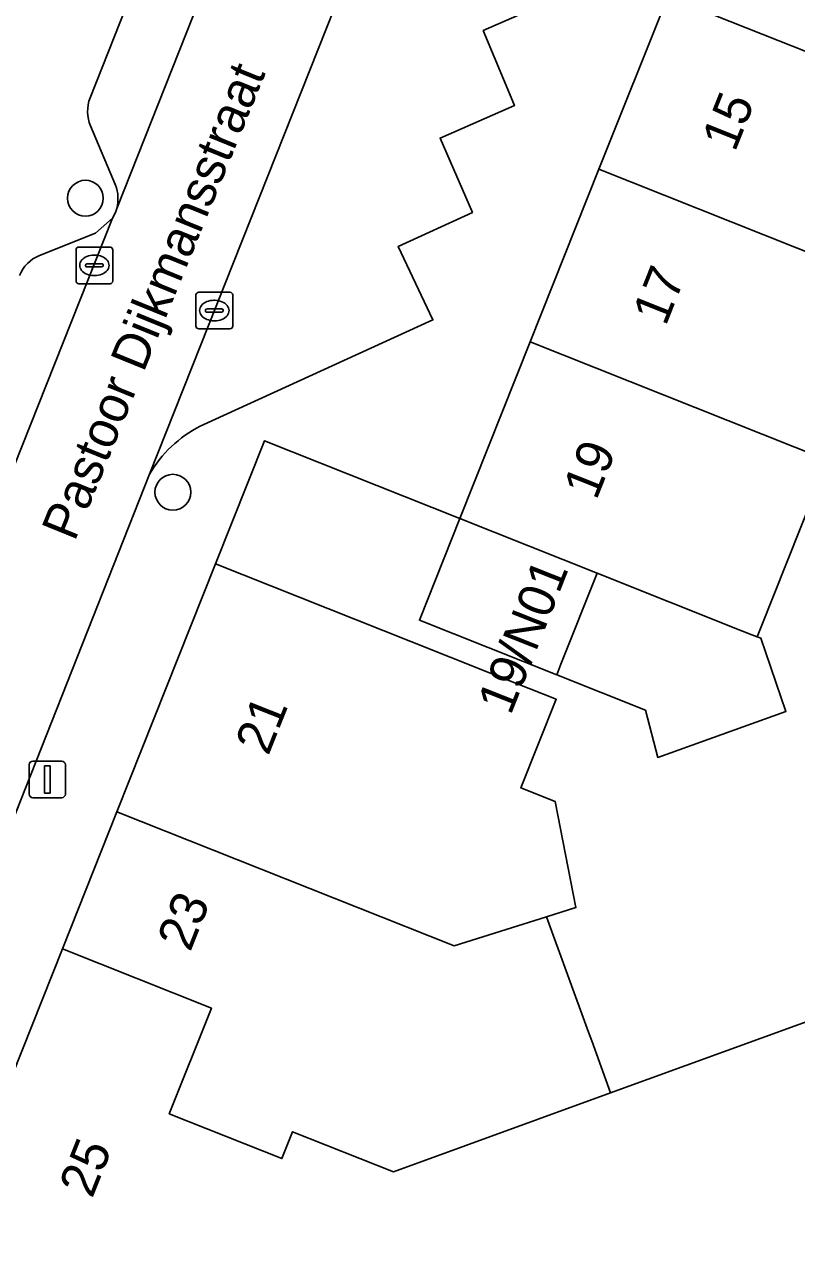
# Model space of a CAD drawing. Extents: x 161798 to 162385, y 382315 to 382833.
# Drawn here: x 162168.1 to 162189.17, y 382526.57 to 382559.91 of the extents above; entities that cross this region are included whole.
import ezdxf

# ---------------------------------------------------------------- set-up
doc = ezdxf.new("R2010")
doc.units = 0
for name, color, linetype in [('IMGEO_Boom', 7, 'Continuous'), ('IMGEO_Erf', 7, 'Continuous'), ('IMGEO_Kolk', 7, 'Continuous'), ('IMGEO_Lichtmast', 7, 'Continuous'), ('IMGEO_Openbare_ruimte_label', 7, 'Continuous'), ('IMGEO_Pand', 7, 'Continuous'), ('IMGEO_Pand_nummerreeks', 7, 'Continuous'), ('IMGEO_Parkeervlak_open', 7, 'Continuous'), ('IMGEO_Rijbaan_lokaal_open', 7, 'Continuous'), ('IMGEO_Voetpad_open', 7, 'Continuous')]:
    doc.layers.add(name, color=color, linetype=linetype)

msp = doc.modelspace()

# ---------------------------------------------------------------- linework, layer by layer
at = {"layer": 'IMGEO_Boom'}
for centre in [(162169.767, 382555.17), (162172.154, 382547.147)]:
    msp.add_circle(centre, 0.489, dxfattribs=at)
at = {"layer": 'IMGEO_Erf'}
msp.add_lwpolyline([(162190.014, 382548.026), (162188.187, 382543.433), (162188.095, 382543.201), (162188.194, 382543.162), (162188.876, 382541.169), (162185.38, 382539.91), (162185.051, 382541.201), (162182.624, 382542.166), (162178.881, 382543.655), (162179.984, 382546.428), (162174.656, 382548.553), (162173.318, 382545.194), (162178.647, 382543.075), (162180.788, 382542.223), (162182.61, 382541.498), (162181.649, 382539.082), (162182.578, 382538.713), (162183.15, 382535.817), (162182.349, 382535.566), (162183.495, 382532.413), (162183.579, 382532.181), (162184.096, 382530.759), (162210.904, 382540.496)], dxfattribs=at)
at = {"layer": 'IMGEO_Kolk'}
for p, q in [((162169.512, 382552.912), (162169.512, 382553.764)), ((162169.587, 382553.838), (162170.439, 382553.838)), ((162170, 382553.618), (162170.025, 382553.618)), ((162170.513, 382553.764), (162170.513, 382552.912)), ((162169.771, 382553.332), (162169.771, 382553.344)), ((162170.209, 382553.295), (162169.811, 382553.295)), ((162169.814, 382553.381), (162170.212, 382553.381)), ((162170.255, 382553.344), (162170.255, 382553.332)), ((162170.023, 382553.058), (162169.998, 382553.058)), ((162170.439, 382552.838), (162169.587, 382552.838)), ((162172.859, 382552.605), (162173.711, 382552.605)), ((162172.784, 382551.679), (162172.784, 382552.531)), ((162173.272, 382552.385), (162173.297, 382552.385)), ((162173.785, 382552.531), (162173.785, 382551.679)), ((162173.043, 382552.099), (162173.043, 382552.111)), ((162173.481, 382552.062), (162173.083, 382552.062)), ((162173.086, 382552.148), (162173.484, 382552.148)), ((162173.527, 382552.111), (162173.527, 382552.099)), ((162173.711, 382551.605), (162172.859, 382551.605)), ((162173.295, 382551.825), (162173.27, 382551.825))]:
    msp.add_line(p, q, dxfattribs=at)
for points in [[(162169.512, 382552.912), (162169.512, 382553.764)], [(162169.587, 382553.838), (162170.439, 382553.838)], [(162170.513, 382553.764), (162170.513, 382552.912)], [(162170.439, 382552.838), (162169.587, 382552.838)], [(162172.859, 382552.605), (162173.711, 382552.605)], [(162172.784, 382551.679), (162172.784, 382552.531)], [(162173.785, 382552.531), (162173.785, 382551.679)], [(162173.711, 382551.605), (162172.859, 382551.605)]]:
    msp.add_lwpolyline(points, dxfattribs=at)
for centre, radius, start, end in [((162169.589, 382553.762), 0.0765, 91.552, 178.448), ((162169.589, 382553.762), 0.0765, 91.552, 178.448), ((162170.437, 382553.762), 0.0765, 1.552, 88.448), ((162170.437, 382553.762), 0.0765, 1.552, 88.448), ((162169.811, 382553.341), 0.0403, 85.8775, 175.7526), ((162169.808, 382553.331), 0.0366, 178.938, 274.7102), ((162170.212, 382553.338), 0.043, 264.8664, 352.4533), ((162170.216, 382553.343), 0.0386, 1.7309, 96.639), ((162169.589, 382552.914), 0.0765, 181.552, 268.448), ((162169.589, 382552.914), 0.0765, 181.552, 268.448), ((162170.437, 382552.914), 0.0765, 271.552, 358.448), ((162170.437, 382552.914), 0.0765, 271.552, 358.448), ((162172.861, 382552.529), 0.0765, 91.552, 178.448), ((162172.861, 382552.529), 0.0765, 91.552, 178.448), ((162173.709, 382552.529), 0.0765, 1.552, 88.448), ((162173.709, 382552.529), 0.0765, 1.552, 88.448), ((162173.083, 382552.108), 0.0403, 85.8775, 175.7526), ((162173.08, 382552.098), 0.0366, 178.938, 274.7102), ((162173.484, 382552.105), 0.043, 264.8664, 352.4533), ((162173.488, 382552.11), 0.0386, 1.7309, 96.639), ((162172.861, 382551.681), 0.0765, 181.552, 268.448), ((162172.861, 382551.681), 0.0765, 181.552, 268.448), ((162173.709, 382551.681), 0.0765, 271.552, 358.448), ((162173.709, 382551.681), 0.0765, 271.552, 358.448)]:
    msp.add_arc(centre, radius, start, end, dxfattribs=at)
for centre, major_axis, ratio, start_param, end_param in [((162169.999, 382553.338), (-0.387, 0.002), 0.722429, 4.712389, 7.853982), ((162170.024, 382553.338), (-0.39, 0.002), 0.717154, 1.570796, 4.712389), ((162173.271, 382552.105), (-0.387, 0.002), 0.722429, 4.712389, 7.853982), ((162173.296, 382552.105), (-0.39, 0.002), 0.717154, 1.570796, 4.712389)]:
    msp.add_ellipse(centre, major_axis=major_axis, ratio=ratio, start_param=start_param, end_param=end_param, dxfattribs=at)
at = {"layer": 'IMGEO_Lichtmast'}
for p, q in [((162168.232, 382538.912), (162168.232, 382539.712)), ((162168.232, 382539.712), (162168.232, 382538.912)), ((162168.332, 382539.812), (162169.122, 382539.812)), ((162169.122, 382539.812), (162168.332, 382539.812)), ((162169.222, 382539.712), (162169.222, 382538.912)), ((162169.222, 382538.912), (162169.222, 382539.712)), ((162169.122, 382538.812), (162168.332, 382538.812)), ((162168.332, 382538.812), (162169.122, 382538.812))]:
    msp.add_line(p, q, dxfattribs=at)
msp.add_lwpolyline([(162168.652, 382539.687), (162168.802, 382539.687), (162168.802, 382538.937), (162168.652, 382538.937), (162168.652, 382539.687)], dxfattribs=at)
for centre, start, end in [((162168.332, 382539.712), 90, 180), ((162168.332, 382539.712), 90, 180), ((162169.122, 382539.712), 0, 90), ((162169.122, 382539.712), 360, 90), ((162168.332, 382538.912), 180, 270), ((162168.332, 382538.912), 180, 270), ((162169.122, 382538.912), 270, 0), ((162169.122, 382538.912), 270, 0)]:
    msp.add_arc(centre, 0.1, start, end, dxfattribs=at)
at = {"layer": 'IMGEO_Pand'}
for points in [[(162195.638, 382562.163), (162187.527, 382565.389), (162185.652, 382560.677), (162193.763, 382557.45)], [(162193.763, 382557.45), (162185.652, 382560.677), (162183.777, 382555.964), (162191.889, 382552.738)], [(162190.014, 382548.026), (162191.889, 382552.738), (162183.777, 382555.964), (162181.903, 382551.252)], [(162190.014, 382548.026), (162181.903, 382551.252), (162179.984, 382546.428), (162183.727, 382544.939), (162187.693, 382543.361), (162187.949, 382543.259), (162188.095, 382543.201), (162188.187, 382543.433)], [(162183.727, 382544.939), (162179.984, 382546.428), (162178.881, 382543.655), (162182.624, 382542.166), (162182.738, 382542.454)], [(162182.61, 382541.498), (162180.788, 382542.223), (162178.647, 382543.075), (162173.318, 382545.194), (162170.627, 382538.431), (162179.823, 382534.773), (162182.349, 382535.566), (162183.15, 382535.817), (162182.578, 382538.713), (162181.649, 382539.082)], [(162188.095, 382543.201), (162187.949, 382543.259), (162187.693, 382543.361), (162183.727, 382544.939), (162182.738, 382542.454), (162182.624, 382542.166), (162185.051, 382541.201), (162185.38, 382539.91), (162188.876, 382541.169), (162188.194, 382543.162)], [(162213.462, 382532.438), (162213.43, 382532.539), (162210.904, 382540.496), (162184.096, 382530.759), (162178.17, 382528.607), (162175.421, 382529.7), (162175.13, 382528.968), (162172.056, 382530.191), (162173.203, 382533.073), (162169.14, 382534.691), (162165.279, 382524.987), (162172.735, 382522.522), (162172.781, 382522.638), (162174.284, 382522.749), (162177.063, 382522.953), (162178.919, 382523.09), (162180.309, 382519.521), (162189.806, 382523.221)], [(162182.349, 382535.566), (162179.823, 382534.773), (162170.627, 382538.431), (162169.14, 382534.691), (162173.203, 382533.073), (162172.056, 382530.191), (162175.13, 382528.968), (162175.421, 382529.7), (162178.17, 382528.607), (162184.096, 382530.759), (162183.579, 382532.181), (162183.495, 382532.413)]]:
    msp.add_lwpolyline(points, close=True, dxfattribs=at)
at = {"layer": 'IMGEO_Parkeervlak_open'}
for points in [[(162170.621, 382554.892), (162178.575, 382574.96)], [(162172.902, 382548.953), (162179.247, 382551.849), (162178.3, 382553.854), (162180.323, 382554.783), (162179.444, 382556.811), (162181.471, 382557.698), (162180.621, 382559.742), (162182.642, 382560.634), (162181.758, 382562.683), (162183.78, 382563.584), (162182.929, 382565.575), (162184.969, 382566.473), (162184.061, 382568.472), (162186.115, 382569.439), (162185.253, 382571.505), (162187.28, 382572.39), (162186.384, 382574.415), (162182.369, 382572.638)], [(162175.91, 382573.119), (162169.897, 382557.907)], [(162181.625, 382573.137), (162171.513, 382547.64)], [(162169.907, 382557.142), (162170.591, 382555.527)], [(162164.884, 382540.483), (162170.508, 382554.627), (162170.044, 382554.215), (162168.511, 382553.603)]]:
    msp.add_lwpolyline(points, dxfattribs=at)
for centre, radius, start, end in [((162170.84, 382557.537), 1.013, 158.5633, 202.9346), ((162169.623, 382555.163), 1.034, 344.8037, 20.6061), ((162168.871, 382552.703), 0.969, 111.7827, 158.3231), ((162174.471, 382545.902), 3.43, 117.2127, 149.565)]:
    msp.add_arc(centre, radius, start, end, dxfattribs=at)
at = {"layer": 'IMGEO_Rijbaan_lokaal_open'}
msp.add_lwpolyline([(162166.587, 382535.18), (162171.513, 382547.64), (162181.625, 382573.137), (162182.222, 382574.642), (162178.971, 382575.905), (162178.575, 382574.96), (162170.621, 382554.892), (162170.585, 382554.784), (162170.508, 382554.627), (162164.884, 382540.483), (162163.254, 382536.338)], close=True, dxfattribs=at)
at = {"layer": 'IMGEO_Voetpad_open'}
for points in [[(162182.369, 382572.638), (162186.384, 382574.415), (162187.28, 382572.39), (162185.253, 382571.505), (162186.115, 382569.439), (162184.061, 382568.472), (162184.969, 382566.473), (162182.929, 382565.575), (162183.78, 382563.584), (162181.758, 382562.683), (162182.642, 382560.634), (162180.621, 382559.742), (162181.471, 382557.698), (162179.444, 382556.811), (162180.323, 382554.783), (162178.3, 382553.854), (162179.247, 382551.849), (162172.902, 382548.953)], [(162169.897, 382557.907), (162175.91, 382573.119)], [(162161.842, 382511.712), (162164.027, 382517.204), (162164.322, 382517.949), (162162.703, 382518.511), (162165.279, 382524.987), (162169.14, 382534.691), (162170.627, 382538.431), (162173.318, 382545.194), (162174.656, 382548.553), (162179.984, 382546.428), (162181.903, 382551.252), (162183.777, 382555.964), (162185.652, 382560.677), (162187.527, 382565.389), (162189.401, 382570.101)], [(162170.591, 382555.527), (162169.907, 382557.142)], [(162168.511, 382553.603), (162170.044, 382554.215), (162170.508, 382554.627), (162170.585, 382554.784), (162170.621, 382554.892)], [(162171.513, 382547.64), (162166.587, 382535.18), (162166.304, 382534.465), (162165.985, 382534.585), (162161.136, 382522.247), (162161.449, 382522.098), (162161.157, 382521.398), (162159.908, 382518.397), (162159.816, 382518.171)]]:
    msp.add_lwpolyline(points, dxfattribs=at)
for centre, radius, start, end in [((162170.84, 382557.537), 1.013, 158.5633, 202.9346), ((162169.623, 382555.163), 1.034, 344.8037, 20.6061), ((162168.871, 382552.703), 0.969, 111.7827, 158.3231), ((162174.471, 382545.902), 3.43, 117.2127, 149.565)]:
    msp.add_arc(centre, radius, start, end, dxfattribs=at)

# ---------------------------------------------------------------- texts
at = {"layer": 'IMGEO_Openbare_ruimte_label'}
msp.add_text('Pastoor Dijkmansstraat', height=1, rotation=67.8474, dxfattribs=at).set_placement((162169.474, 382545.78))
at = {"layer": 'IMGEO_Pand_nummerreeks'}
for s, rotation, p in [('15', 68.3075, (162187.484, 382556.406)), ('17', 68.3075, (162185.595, 382551.656)), ('19', 68.308, (162183.705, 382546.907)), ('19/N01', 68.3768, (162181.366, 382541.038)), ('21', 68.3023, (162174.756, 382539.936)), ('23', 68.3195, (162172.626, 382534.582)), ('25', 68.3023, (162169.951, 382527.858))]:
    msp.add_text(s, height=1, rotation=rotation, dxfattribs=at).set_placement(p)

doc.saveas('drawing.dxf')
